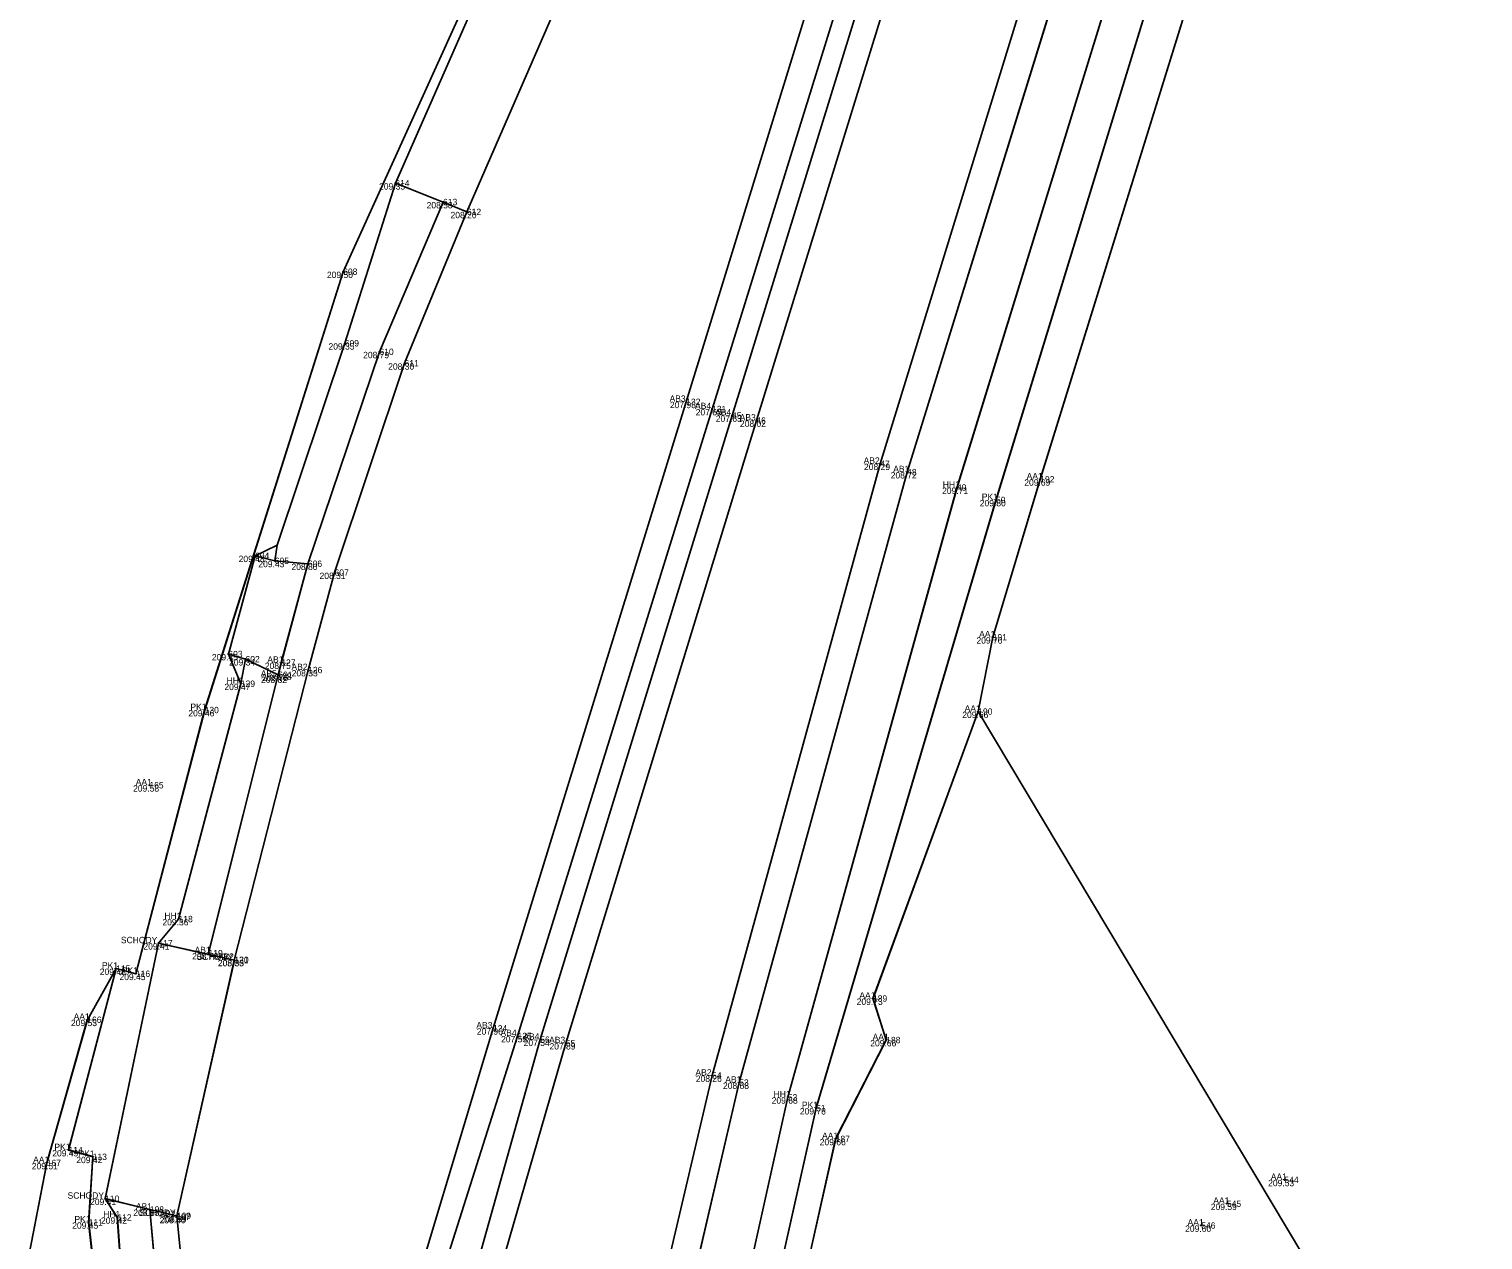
# Model space of a CAD drawing. Extents: x -263091 to -262565, y -1238731 to -1237092.
# Drawn here: x -262956.55 to -262910.85, y -1238367.34 to -1238329.27 of the extents above; entities that cross this region are included whole.
import ezdxf

# ---------------------------------------------------------------- set-up
doc = ezdxf.new("R2010")
doc.units = 0
for name, color, linetype in [('01_Hrana_betónu', 7, 'Continuous'), ('02_Oplotenie', 7, 'Continuous'), ('03_Asfalt', 7, 'Continuous'), ('05_Hrana_terénu', 7, 'Continuous'), ('06_Schody', 7, 'Continuous'), ('07_Iné', 7, 'Continuous'), ('Groma (21)', 7, 'Continuous'), ('Groma (22)', 7, 'Continuous'), ('Groma (23)', 7, 'Continuous'), ('Groma (24)', 7, 'Continuous'), ('U002_Asfalt', 7, 'Continuous'), ('U002_Betónové panely', 7, 'Continuous'), ('U002_Betóny_prídavné', 7, 'Continuous'), ('U002_Schody', 7, 'Continuous'), ('U002_Zeleň_mimo', 7, 'Continuous'), ('U002_Zeleň_vnútro', 7, 'Continuous'), ('U002_Zeleň_zatrávňovač', 7, 'Continuous')]:
    doc.layers.add(name, color=color, linetype=linetype)

msp = doc.modelspace()

# ---------------------------------------------------------------- linework, layer by layer
at = {"layer": '01_Hrana_betónu'}
for points in [[(-262944.213, -1238387.387), (-262944.634, -1238381.789), (-262944.5, -1238371.343), (-262941.2, -1238360.927), (-262935.086, -1238341.218), (-262927.632, -1238317.179), (-262920.793, -1238295.265), (-262911.171, -1238262.813), (-262915.352, -1238261.064), (-262915.337, -1238259.329), (-262909.866, -1238261.629), (-262904.904, -1238263.716)], [(-262916.095, -1238261.519), (-262911.974, -1238263.293), (-262921.591, -1238294.909), (-262928.534, -1238317.073), (-262935.896, -1238340.99), (-262941.971, -1238360.685), (-262945.096, -1238371.115), (-262945.34, -1238381.803), (-262945.412, -1238387.557)], [(-262941.714, -1238387.032), (-262942.991, -1238380.859), (-262943.934, -1238373.35), (-262940.485, -1238361.041), (-262934.456, -1238341.421), (-262927.277, -1238318.134), (-262920.116, -1238294.802), (-262913.64, -1238273.614), (-262910.214, -1238263.245), (-262905.769, -1238265.099), (-262904.904, -1238263.716)], [(-262905.769, -1238265.099), (-262909.81, -1238264.181), (-262912.956, -1238273.861), (-262919.396, -1238295.066), (-262926.538, -1238318.409), (-262933.693, -1238341.579), (-262939.683, -1238361.151), (-262943.246, -1238373.477), (-262942.259, -1238380.752), (-262940.526, -1238386.713)], [(-262905.769, -1238265.099), (-262909.014, -1238275.12), (-262915.393, -1238296.189), (-262922.597, -1238319.497), (-262929.796, -1238342.936), (-262935.083, -1238362.17), (-262937.995, -1238374.567), (-262938.788, -1238380.26), (-262939.46, -1238386.668), (-262940.526, -1238386.713), (-262940.498, -1238386.859)], [(-262940.36, -1238387.407), (-262939.388, -1238387.391), (-262938.822, -1238386.902), (-262937.88, -1238380.385), (-262937.119, -1238374.802), (-262934.23, -1238362.39), (-262928.952, -1238343.2), (-262921.717, -1238319.813), (-262915.107, -1238298.192), (-262908.208, -1238275.423), (-262904.855, -1238265.436)], [(-262950.921, -1238358.358), (-262948.72, -1238349.57), (-262948.626, -1238349.19), (-262947.79, -1238346.08), (-262945.54, -1238339.42), (-262943.54, -1238334.71)], [(-262950.104, -1238358.539), (-262947.782, -1238349.422), (-262946.95, -1238346.36), (-262944.75, -1238339.78), (-262942.79, -1238335.02)], [(-262945.333, -1238387.95), (-262946.617, -1238387.98), (-262947.712, -1238387.066), (-262949.402, -1238383.422), (-262952.187, -1238372.656), (-262952.759, -1238366.382)], [(-262951.91, -1238366.581), (-262951.321, -1238372.499), (-262948.634, -1238383.126), (-262947.098, -1238386.578), (-262946.426, -1238387.428), (-262945.412, -1238387.557)]]:
    msp.add_lwpolyline(points, dxfattribs=at)
at = {"layer": '02_Oplotenie'}
msp.add_lwpolyline([(-262939.39, -1238320.83), (-262941.19, -1238324.79), (-262946.68, -1238336.9), (-262951.035, -1238350.68), (-262953.195, -1238358.97), (-262953.815, -1238358.809), (-262955.312, -1238364.513), (-262954.553, -1238364.724), (-262954.681, -1238366.785), (-262954.024, -1238372.698), (-262951.104, -1238384.342), (-262949.016, -1238390.045), (-262944.443, -1238389.969), (-262936.906, -1238389.616), (-262935.581, -1238380.82), (-262934.566, -1238375.513), (-262931.812, -1238363.194), (-262926.159, -1238344.076), (-262918.903, -1238320.384), (-262912.242, -1238298.942), (-262905.326, -1238276.054), (-262902.598, -1238266.292), (-262902.107, -1238264.892)], dxfattribs=at)
at = {"layer": '03_Asfalt'}
for points in [[(-262917.941, -1238321.4), (-262924.768, -1238343.427), (-262926.262, -1238348.392), (-262926.717, -1238350.729), (-262930.026, -1238359.749), (-262929.61, -1238361.054), (-262931.199, -1238364.162), (-262933.003, -1238372.216)], [(-262956.554, -1238367.788), (-262955.999, -1238364.917), (-262954.725, -1238360.416)]]:
    msp.add_lwpolyline(points, dxfattribs=at)
at = {"layer": '05_Hrana_terénu'}
msp.add_lwpolyline([(-262920.126, -1238320.151), (-262927.385, -1238343.686), (-262932.704, -1238362.854), (-262935.453, -1238375.219), (-262936.279, -1238380.57), (-262937.519, -1238387.253), (-262938.314, -1238388.733), (-262939.759, -1238389.403), (-262945.681, -1238389.45), (-262947.587, -1238388.865), (-262949.049, -1238387.288), (-262950.436, -1238384.21), (-262953.347, -1238372.702), (-262953.777, -1238366.63), (-262954.163, -1238366.041), (-262952.487, -1238358.01), (-262951.855, -1238357.25), (-262949.897, -1238349.853), (-262950.29, -1238348.92), (-262949.45, -1238345.83), (-262948.76, -1238345.496), (-262946.63, -1238339.15), (-262945.04, -1238334.12), (-262941.75, -1238326.63)], dxfattribs=at)
at = {"layer": '06_Schody'}
for points in [[(-262942.79, -1238335.02), (-262943.54, -1238334.71), (-262945.04, -1238334.12), (-262941.75, -1238326.63), (-262940.4, -1238327.16), (-262939.53, -1238327.53)], [(-262951.91, -1238366.581), (-262952.759, -1238366.382), (-262954.163, -1238366.041), (-262952.487, -1238358.01), (-262950.921, -1238358.358), (-262950.104, -1238358.539)]]:
    msp.add_lwpolyline(points, close=True, dxfattribs=at)
at = {"layer": '07_Iné'}
msp.add_lwpolyline([(-262948.72, -1238349.57), (-262949.75, -1238349.08), (-262950.29, -1238348.92), (-262949.45, -1238345.83), (-262948.83, -1238345.99), (-262947.79, -1238346.08)], dxfattribs=at)
at = {"layer": 'Groma (21)'}
for centre in [(-262945.04, -1238334.12), (-262943.54, -1238334.71), (-262942.79, -1238335.02), (-262946.68, -1238336.9), (-262946.63, -1238339.15), (-262945.54, -1238339.42), (-262944.75, -1238339.78), (-262935.896, -1238340.99), (-262935.086, -1238341.218), (-262934.456, -1238341.421), (-262933.693, -1238341.579), (-262929.796, -1238342.936), (-262928.952, -1238343.2), (-262924.768, -1238343.427), (-262927.385, -1238343.686), (-262926.159, -1238344.076), (-262949.45, -1238345.83), (-262948.83, -1238345.99), (-262947.79, -1238346.08), (-262946.95, -1238346.36), (-262926.262, -1238348.392), (-262950.29, -1238348.92), (-262949.75, -1238349.08), (-262948.626, -1238349.19), (-262947.782, -1238349.422), (-262949.897, -1238349.853), (-262948.747, -1238349.629), (-262948.72, -1238349.57), (-262951.035, -1238350.68), (-262926.717, -1238350.729), (-262952.772, -1238353.044), (-262951.855, -1238357.25), (-262952.487, -1238358.01), (-262950.912, -1238358.322), (-262950.104, -1238358.539), (-262950.099, -1238358.531), (-262953.815, -1238358.809), (-262953.195, -1238358.97), (-262930.026, -1238359.749), (-262954.725, -1238360.416), (-262941.971, -1238360.685), (-262941.2, -1238360.927), (-262940.485, -1238361.041), (-262939.683, -1238361.151), (-262929.61, -1238361.054), (-262935.083, -1238362.17), (-262934.23, -1238362.39), (-262932.704, -1238362.854), (-262931.812, -1238363.194), (-262955.312, -1238364.513), (-262931.199, -1238364.162), (-262955.999, -1238364.917), (-262954.553, -1238364.724), (-262917.093, -1238365.449), (-262954.163, -1238366.041), (-262952.759, -1238366.382), (-262918.901, -1238366.199), (-262954.681, -1238366.785), (-262953.777, -1238366.63), (-262951.932, -1238366.616), (-262951.91, -1238366.581), (-262919.709, -1238366.884)]:
    msp.add_circle(centre, 0.01, dxfattribs=at)
at = {"layer": 'U002_Asfalt'}
msp.add_lwpolyline([(-262933, -1238372.22), (-262931.2, -1238364.16), (-262929.61, -1238361.05), (-262930.03, -1238359.75), (-262926.72, -1238350.73), (-262915.49, -1238369.52)], dxfattribs=at)
msp.add_lwpolyline([(-262933, -1238372.22), (-262931.2, -1238364.16), (-262929.61, -1238361.05), (-262930.03, -1238359.75), (-262926.72, -1238350.73), (-262915.49, -1238369.52)], dxfattribs=at)
at = {"layer": 'U002_Betónové panely'}
for points in [[(-262921.72, -1238319.81), (-262928.95, -1238343.2), (-262934.23, -1238362.39), (-262937.12, -1238374.8)], [(-262921.72, -1238319.81), (-262928.95, -1238343.2), (-262934.23, -1238362.39), (-262937.12, -1238374.8)], [(-262952.19, -1238372.66), (-262952.76, -1238366.38), (-262951.91, -1238366.58), (-262950.1, -1238358.54), (-262950.92, -1238358.36), (-262948.72, -1238349.57), (-262948.63, -1238349.19), (-262947.79, -1238346.08), (-262945.54, -1238339.42), (-262943.54, -1238334.71), (-262942.79, -1238335.02), (-262939.53, -1238327.53)], [(-262952.19, -1238372.66), (-262952.76, -1238366.38), (-262951.91, -1238366.58), (-262950.1, -1238358.54), (-262950.92, -1238358.36), (-262948.72, -1238349.57), (-262948.63, -1238349.19), (-262947.79, -1238346.08), (-262945.54, -1238339.42), (-262943.54, -1238334.71), (-262942.79, -1238335.02), (-262939.53, -1238327.53)]]:
    msp.add_lwpolyline(points, dxfattribs=at)
at = {"layer": 'U002_Betóny_prídavné'}
msp.add_lwpolyline([(-262948.72, -1238349.57), (-262949.75, -1238349.08), (-262950.29, -1238348.92), (-262949.45, -1238345.83), (-262948.83, -1238345.99), (-262947.79, -1238346.08)], close=True, dxfattribs=at)
msp.add_lwpolyline([(-262948.72, -1238349.57), (-262949.75, -1238349.08), (-262950.29, -1238348.92), (-262949.45, -1238345.83), (-262948.83, -1238345.99), (-262947.79, -1238346.08), (-262948.72, -1238349.57)], dxfattribs=at)
at = {"layer": 'U002_Schody'}
for points in [[(-262943.54, -1238334.71), (-262945.04, -1238334.12), (-262941.75, -1238326.63), (-262940.4, -1238327.16), (-262939.53, -1238327.53), (-262942.79, -1238335.02)], [(-262950.1, -1238358.54), (-262951.91, -1238366.58), (-262952.76, -1238366.38), (-262954.16, -1238366.04), (-262952.49, -1238358.01), (-262950.92, -1238358.36)]]:
    msp.add_lwpolyline(points, close=True, dxfattribs=at)
for points in [[(-262942.79, -1238335.02), (-262943.54, -1238334.71), (-262945.04, -1238334.12), (-262941.75, -1238326.63), (-262940.4, -1238327.16), (-262939.53, -1238327.53), (-262942.79, -1238335.02)], [(-262951.91, -1238366.58), (-262952.76, -1238366.38), (-262954.16, -1238366.04), (-262952.49, -1238358.01), (-262950.92, -1238358.36), (-262950.1, -1238358.54), (-262951.91, -1238366.58)]]:
    msp.add_lwpolyline(points, dxfattribs=at)
at = {"layer": 'U002_Zeleň_mimo'}
for points in [[(-262934.57, -1238375.51), (-262931.81, -1238363.19), (-262926.16, -1238344.08), (-262918.9, -1238320.38)], [(-262917.94, -1238321.4), (-262924.77, -1238343.43), (-262926.26, -1238348.39), (-262926.72, -1238350.73), (-262930.03, -1238359.75), (-262929.61, -1238361.05), (-262931.2, -1238364.16), (-262933, -1238372.22)], [(-262956.55, -1238367.79), (-262956, -1238364.92), (-262954.72, -1238360.42), (-262953.82, -1238358.81), (-262955.31, -1238364.51), (-262954.55, -1238364.72), (-262954.68, -1238366.78), (-262954.02, -1238372.7)]]:
    msp.add_lwpolyline(points, dxfattribs=at)
at = {"layer": 'U002_Zeleň_vnútro'}
for points in [[(-262935.45, -1238375.22), (-262932.7, -1238362.85), (-262927.39, -1238343.69), (-262920.13, -1238320.15)], [(-262935.45, -1238375.22), (-262932.7, -1238362.85), (-262927.39, -1238343.69), (-262920.13, -1238320.15)], [(-262918.9, -1238320.38), (-262926.16, -1238344.08), (-262931.81, -1238363.19), (-262934.57, -1238375.51), (-262935.58, -1238380.82), (-262936.91, -1238389.62), (-262944.44, -1238389.97), (-262949.02, -1238390.05), (-262951.1, -1238384.34), (-262954.02, -1238372.7), (-262954.68, -1238366.78), (-262954.55, -1238364.72), (-262955.31, -1238364.51), (-262953.82, -1238358.81), (-262953.2, -1238358.97), (-262951.03, -1238350.68), (-262946.68, -1238336.9), (-262941.19, -1238324.79)], [(-262918.9, -1238320.38), (-262926.16, -1238344.08), (-262931.81, -1238363.19), (-262934.57, -1238375.51), (-262935.58, -1238380.82), (-262936.91, -1238389.62), (-262944.44, -1238389.97), (-262949.02, -1238390.05)], [(-262949.02, -1238390.05), (-262951.1, -1238384.34), (-262954.02, -1238372.7), (-262954.68, -1238366.78), (-262954.55, -1238364.72), (-262955.31, -1238364.51), (-262953.82, -1238358.81), (-262953.2, -1238358.97), (-262951.03, -1238350.68), (-262946.68, -1238336.9), (-262941.19, -1238324.79)], [(-262941.75, -1238326.63), (-262945.04, -1238334.12), (-262946.63, -1238339.15), (-262948.76, -1238345.5), (-262948.83, -1238345.99), (-262949.45, -1238345.83), (-262950.29, -1238348.92), (-262949.75, -1238349.08), (-262949.9, -1238349.85), (-262951.86, -1238357.25), (-262952.49, -1238358.01), (-262954.16, -1238366.04), (-262953.78, -1238366.63), (-262953.35, -1238372.7)], [(-262941.75, -1238326.63), (-262945.04, -1238334.12), (-262946.63, -1238339.15), (-262948.76, -1238345.5), (-262948.83, -1238345.99), (-262949.45, -1238345.83), (-262950.29, -1238348.92), (-262949.75, -1238349.08), (-262949.9, -1238349.85), (-262951.86, -1238357.25), (-262952.49, -1238358.01), (-262954.16, -1238366.04), (-262953.78, -1238366.63), (-262953.35, -1238372.7)]]:
    msp.add_lwpolyline(points, dxfattribs=at)
at = {"layer": 'U002_Zeleň_zatrávňovač'}
for points in [[(-262945.68, -1238389.45), (-262947.59, -1238388.87), (-262949.05, -1238387.29), (-262950.44, -1238384.21), (-262953.35, -1238372.7), (-262953.78, -1238366.63), (-262954.16, -1238366.04), (-262952.76, -1238366.38), (-262952.19, -1238372.66), (-262949.4, -1238383.42), (-262947.71, -1238387.07), (-262946.62, -1238387.98), (-262945.33, -1238387.95), (-262940.41, -1238387.31), (-262940.36, -1238387.41), (-262939.39, -1238387.39), (-262938.82, -1238386.9), (-262937.88, -1238380.39), (-262937.12, -1238374.8), (-262934.23, -1238362.39), (-262928.95, -1238343.2), (-262921.72, -1238319.81)], [(-262920.13, -1238320.15), (-262927.39, -1238343.69), (-262932.7, -1238362.85), (-262935.45, -1238375.22), (-262936.28, -1238380.57), (-262937.52, -1238387.25), (-262938.31, -1238388.73), (-262939.76, -1238389.4), (-262945.68, -1238389.45)], [(-262937.12, -1238374.8), (-262934.23, -1238362.39), (-262928.95, -1238343.2), (-262921.72, -1238319.81)], [(-262920.13, -1238320.15), (-262927.39, -1238343.69), (-262932.7, -1238362.85), (-262935.45, -1238375.22)], [(-262947.79, -1238346.08), (-262948.83, -1238345.99), (-262948.76, -1238345.5), (-262946.63, -1238339.15), (-262945.04, -1238334.12), (-262943.54, -1238334.71), (-262945.54, -1238339.42), (-262947.79, -1238346.08)], [(-262950.92, -1238358.36), (-262952.49, -1238358.01), (-262951.86, -1238357.25), (-262949.9, -1238349.85), (-262949.75, -1238349.08), (-262948.72, -1238349.57), (-262950.92, -1238358.36)], [(-262953.35, -1238372.7), (-262953.78, -1238366.63), (-262954.16, -1238366.04), (-262952.76, -1238366.38), (-262952.19, -1238372.66)]]:
    msp.add_lwpolyline(points, dxfattribs=at)
for points in [[(-262946.63, -1238339.15), (-262945.04, -1238334.12), (-262943.54, -1238334.71), (-262945.54, -1238339.42), (-262947.79, -1238346.08), (-262948.83, -1238345.99), (-262948.76, -1238345.5)], [(-262949.75, -1238349.08), (-262948.72, -1238349.57), (-262950.92, -1238358.36), (-262952.49, -1238358.01), (-262951.86, -1238357.25), (-262949.9, -1238349.85)]]:
    msp.add_lwpolyline(points, close=True, dxfattribs=at)

# ---------------------------------------------------------------- texts
at = {"layer": 'Groma (22)'}
for s, p in [('614', (-262945.04, -1238334.22)), ('613', (-262943.54, -1238334.81)), ('612', (-262942.79, -1238335.12)), ('608', (-262946.68, -1238337)), ('609', (-262946.63, -1238339.25)), ('610', (-262945.54, -1238339.52)), ('611', (-262944.75, -1238339.88)), ('132', (-262935.896, -1238341.09)), ('131', (-262935.086, -1238341.318)), ('45', (-262934.456, -1238341.521)), ('46', (-262933.693, -1238341.679)), ('47', (-262929.796, -1238343.036)), ('48', (-262928.952, -1238343.3)), ('192', (-262924.768, -1238343.527)), ('49', (-262927.385, -1238343.786)), ('50', (-262926.159, -1238344.176)), ('604', (-262949.45, -1238345.93)), ('605', (-262948.83, -1238346.09)), ('606', (-262947.79, -1238346.18)), ('607', (-262946.95, -1238346.46)), ('191', (-262926.262, -1238348.492)), ('603', (-262950.29, -1238349.02)), ('602', (-262949.75, -1238349.18)), ('601', (-262948.72, -1238349.67)), ('127', (-262948.626, -1238349.29)), ('126', (-262947.782, -1238349.522)), ('129', (-262949.897, -1238349.953)), ('128', (-262948.747, -1238349.729)), ('130', (-262951.035, -1238350.78)), ('190', (-262926.717, -1238350.829)), ('165', (-262952.772, -1238353.144)), ('118', (-262951.855, -1238357.35)), ('117', (-262952.487, -1238358.11)), ('119', (-262950.912, -1238358.422)), ('121', (-262950.104, -1238358.639)), ('120', (-262950.099, -1238358.631)), ('115', (-262953.815, -1238358.909)), ('116', (-262953.195, -1238359.07)), ('189', (-262930.026, -1238359.849)), ('166', (-262954.725, -1238360.516)), ('124', (-262941.971, -1238360.785)), ('125', (-262941.2, -1238361.027)), ('56', (-262940.485, -1238361.141)), ('55', (-262939.683, -1238361.251)), ('188', (-262929.61, -1238361.154)), ('54', (-262935.083, -1238362.27)), ('53', (-262934.23, -1238362.49)), ('52', (-262932.704, -1238362.954)), ('51', (-262931.812, -1238363.294)), ('187', (-262931.199, -1238364.262)), ('114', (-262955.312, -1238364.613)), ('167', (-262955.999, -1238365.017)), ('113', (-262954.553, -1238364.824)), ('544', (-262917.093, -1238365.549)), ('110', (-262954.163, -1238366.141)), ('108', (-262952.759, -1238366.482)), ('545', (-262918.901, -1238366.299)), ('111', (-262954.681, -1238366.885)), ('112', (-262953.777, -1238366.73)), ('107', (-262951.932, -1238366.716)), ('109', (-262951.91, -1238366.681)), ('546', (-262919.709, -1238366.984))]:
    msp.add_text(s, height=0.2, dxfattribs=at).set_placement(p)
at = {"layer": 'Groma (23)'}
for s, p in [('209.35', (-262945.552, -1238334.32)), ('208.58', (-262944.057, -1238334.91)), ('208.20', (-262943.306, -1238335.22)), ('209.50', (-262947.191, -1238337.1)), ('209.35', (-262947.142, -1238339.35)), ('208.79', (-262946.053, -1238339.62)), ('208.30', (-262945.266, -1238339.98)), ('207.98', (-262936.409, -1238341.19)), ('207.65', (-262935.599, -1238341.418)), ('207.63', (-262934.969, -1238341.621)), ('208.02', (-262934.209, -1238341.779)), ('208.29', (-262930.308, -1238343.136)), ('208.72', (-262929.469, -1238343.4)), ('209.69', (-262925.27, -1238343.627)), ('209.71', (-262927.854, -1238343.886)), ('209.80', (-262926.67, -1238344.276)), ('209.48', (-262949.967, -1238346.03)), ('209.43', (-262949.347, -1238346.19)), ('208.80', (-262948.306, -1238346.28)), ('208.31', (-262947.423, -1238346.56)), ('209.70', (-262926.774, -1238348.592)), ('209.45', (-262950.807, -1238349.12)), ('209.34', (-262950.267, -1238349.28)), ('208.75', (-262949.143, -1238349.39)), ('208.33', (-262948.299, -1238349.622)), ('209.47', (-262950.414, -1238350.053)), ('208.82', (-262949.264, -1238349.829)), ('208.76', (-262949.233, -1238349.77)), ('209.46', (-262951.547, -1238350.88)), ('209.66', (-262927.219, -1238350.929)), ('209.58', (-262953.284, -1238353.244)), ('209.36', (-262952.362, -1238357.45)), ('209.41', (-262952.96, -1238358.21)), ('208.70', (-262951.429, -1238358.522)), ('208.33', (-262950.621, -1238358.739)), ('208.33', (-262950.616, -1238358.731)), ('209.48', (-262954.332, -1238359.009)), ('209.45', (-262953.712, -1238359.17)), ('209.73', (-262930.539, -1238359.949)), ('209.53', (-262955.237, -1238360.616)), ('207.96', (-262942.479, -1238360.885)), ('207.53', (-262941.717, -1238361.127)), ('207.54', (-262941.007, -1238361.241)), ('207.89', (-262940.196, -1238361.351)), ('209.66', (-262930.112, -1238361.254)), ('208.26', (-262935.595, -1238362.37)), ('208.68', (-262934.742, -1238362.59)), ('209.68', (-262933.211, -1238363.054)), ('209.78', (-262932.325, -1238363.394)), ('209.49', (-262955.824, -1238364.713)), ('209.66', (-262931.701, -1238364.362)), ('209.51', (-262956.467, -1238365.117)), ('209.42', (-262955.07, -1238364.924)), ('209.53', (-262917.605, -1238365.649)), ('209.41', (-262954.636, -1238366.241)), ('208.85', (-262953.276, -1238366.582)), ('209.59', (-262919.408, -1238366.399)), ('209.45', (-262955.198, -1238366.985)), ('209.42', (-262954.294, -1238366.83)), ('208.40', (-262952.452, -1238366.816)), ('208.39', (-262952.422, -1238366.781)), ('209.60', (-262920.215, -1238367.084))]:
    msp.add_text(s, height=0.2, dxfattribs=at).set_placement(p)
at = {"layer": 'Groma (24)'}
for s, p in [('AB3', (-262936.42, -1238340.99)), ('AB4', (-262935.62, -1238341.218)), ('AB4', (-262934.99, -1238341.421)), ('AB3', (-262934.217, -1238341.579)), ('AB2', (-262930.32, -1238342.936)), ('AB1', (-262929.39, -1238343.2)), ('HH1', (-262927.832, -1238343.686)), ('AA1', (-262925.196, -1238343.427)), ('PK1', (-262926.606, -1238344.076)), ('AA1', (-262926.69, -1238348.392)), ('AB1', (-262949.064, -1238349.19)), ('AB5', (-262949.271, -1238349.629)), ('AB2', (-262948.306, -1238349.422)), ('HH1', (-262950.344, -1238349.853)), ('PK1', (-262951.482, -1238350.68)), ('AA1', (-262927.145, -1238350.729)), ('AA1', (-262953.2, -1238353.044)), ('HH1', (-262952.302, -1238357.25)), ('SCHODY', (-262953.668, -1238358.01)), ('AB1', (-262951.35, -1238358.322)), ('PK1', (-262954.262, -1238358.809)), ('SCHODY', (-262951.285, -1238358.539)), ('AB2', (-262950.623, -1238358.531)), ('PK1', (-262953.642, -1238358.97)), ('AA1', (-262930.454, -1238359.749)), ('AA1', (-262955.153, -1238360.416)), ('AB3', (-262942.495, -1238360.685)), ('AB4', (-262941.734, -1238360.927)), ('AB4', (-262941.019, -1238361.041)), ('AA1', (-262930.038, -1238361.054)), ('AB3', (-262940.207, -1238361.151)), ('AB2', (-262935.607, -1238362.17)), ('AB1', (-262934.668, -1238362.39)), ('HH1', (-262933.151, -1238362.854)), ('PK1', (-262932.259, -1238363.194)), ('AA1', (-262931.627, -1238364.162)), ('PK1', (-262955.759, -1238364.513)), ('PK1', (-262955, -1238364.724)), ('AA1', (-262956.427, -1238364.917)), ('AA1', (-262917.521, -1238365.449)), ('SCHODY', (-262955.344, -1238366.041)), ('AB1', (-262953.197, -1238366.382)), ('SCHODY', (-262953.091, -1238366.581)), ('AA1', (-262919.329, -1238366.199)), ('PK1', (-262955.128, -1238366.785)), ('HH1', (-262954.224, -1238366.63)), ('AB2', (-262952.456, -1238366.616)), ('AA1', (-262920.137, -1238366.884))]:
    msp.add_text(s, height=0.2, dxfattribs=at).set_placement(p)

doc.saveas('drawing.dxf')
